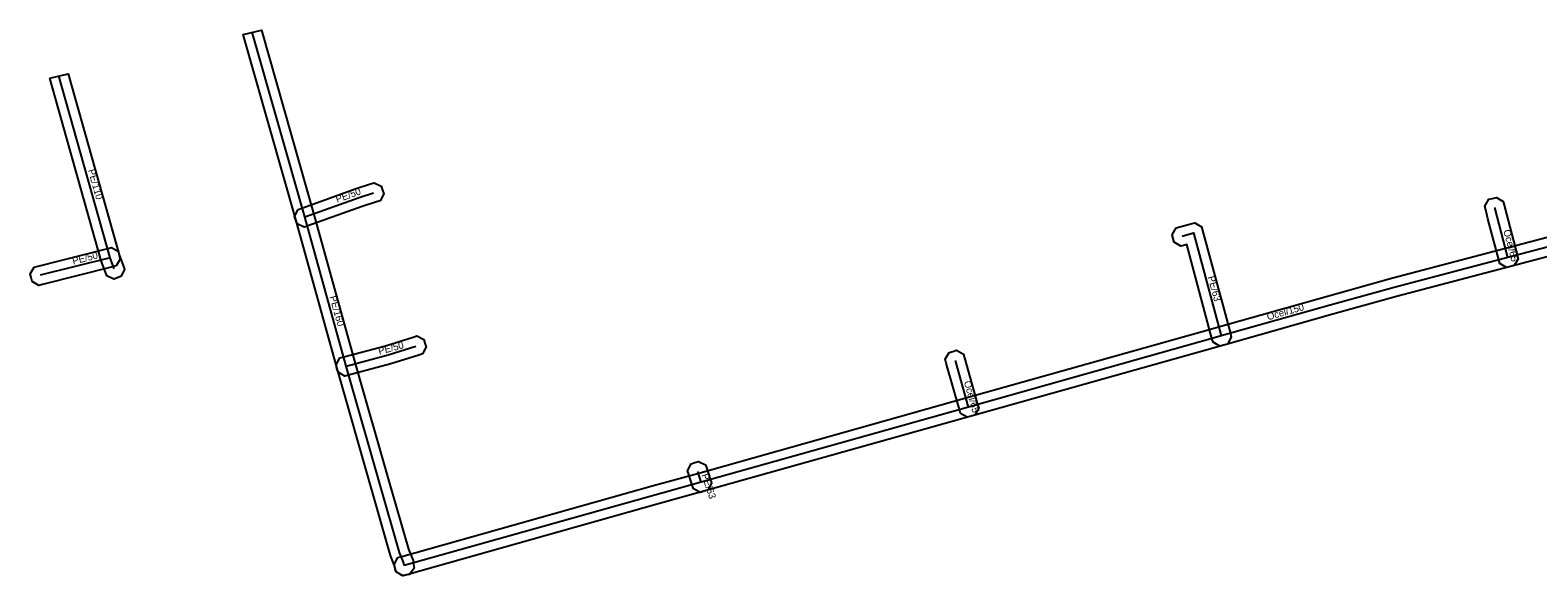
# Model space of a CAD drawing. Extents: x -599265 to -598944, y -1158962 to -1158820.
# Drawn here: x -599265.1 to -599106.1, y -1158937 to -1158879.4 of the extents above; entities that cross this region are included whole.
import ezdxf

# ---------------------------------------------------------------- set-up
doc = ezdxf.new("R2010")
doc.units = 0
for name, color, linetype in [('1', 7, 'Continuous'), ('14', 7, 'Continuous'), ('20', 7, 'Continuous')]:
    doc.layers.add(name, color=color, linetype=linetype)

msp = doc.modelspace()

# ---------------------------------------------------------------- linework, layer by layer
at = {"layer": '1'}
for points in [[(-599237.09, -1158899.41), (-599242.65, -1158879.89), (-599240.7, -1158879.45), (-599235.17, -1158898.87), (-599230.81, -1158914.59), (-599227.26, -1158927), (-599225.2, -1158934.18), (-599224.72, -1158935.37), (-599224.66, -1158935.75), (-599224.6, -1158936.16), (-599225.09, -1158936.82), (-599225.5, -1158936.89), (-599225.91, -1158936.95), (-599226.58, -1158936.46), (-599226.64, -1158936.05), (-599226.66, -1158935.91), (-599227.1, -1158934.84), (-599229.18, -1158927.54), (-599232.73, -1158915.13)], [(-599263.03, -1158884.5), (-599261.07, -1158884.05), (-599255.71, -1158903.13), (-599255.28, -1158904.26), (-599255.14, -1158904.65), (-599255.48, -1158905.4), (-599255.87, -1158905.55), (-599256.26, -1158905.69), (-599257.01, -1158905.35), (-599257.16, -1158904.96), (-599257.61, -1158903.75)], [(-599236.85, -1158898.34), (-599236.46, -1158898.2), (-599230.72, -1158896.15), (-599229.2, -1158895.66), (-599228.81, -1158895.53), (-599228.07, -1158895.91), (-599227.94, -1158896.3), (-599227.81, -1158896.7), (-599228.19, -1158897.43), (-599228.58, -1158897.56), (-599230.08, -1158898.05), (-599235.8, -1158900.08), (-599236.19, -1158900.22), (-599236.93, -1158899.86), (-599237.07, -1158899.48), (-599237.21, -1158899.08)], [(-599110.14, -1158904.06), (-599110.25, -1158903.66), (-599111.39, -1158899.35), (-599111.63, -1158898.4), (-599111.73, -1158897.99), (-599111.31, -1158897.28), (-599110.91, -1158897.18), (-599110.5, -1158897.08), (-599109.79, -1158897.5), (-599109.69, -1158897.91), (-599109.45, -1158898.85), (-599108.31, -1158903.14), (-599108.21, -1158903.54), (-599108.62, -1158904.26), (-599109.02, -1158904.37), (-599109.42, -1158904.47)], [(-599144.28, -1158900.3), (-599143.88, -1158900.19), (-599142.7, -1158899.87), (-599142.3, -1158899.76), (-599141.95, -1158899.97), (-599141.58, -1158900.18), (-599141.48, -1158900.57), (-599138.55, -1158911.43), (-599138.45, -1158911.83), (-599138.86, -1158912.54), (-599139.26, -1158912.65), (-599139.66, -1158912.76), (-599140.38, -1158912.35), (-599140.49, -1158911.95), (-599143.15, -1158902.06), (-599143.36, -1158902.12), (-599143.76, -1158902.23), (-599144.47, -1158901.81), (-599144.58, -1158901.41), (-599144.69, -1158901.01)], [(-599256.01, -1158904.31), (-599256.42, -1158904.41), (-599263.78, -1158906.26), (-599264.18, -1158906.36), (-599264.89, -1158905.94), (-599264.99, -1158905.53), (-599265.09, -1158905.13), (-599264.67, -1158904.42), (-599264.26, -1158904.32), (-599256.9, -1158902.47), (-599256.5, -1158902.37), (-599255.79, -1158902.79), (-599255.69, -1158903.2), (-599255.59, -1158903.6)], [(-599232.43, -1158914), (-599232.03, -1158913.89), (-599227.61, -1158912.71), (-599224.72, -1158911.8), (-599224.33, -1158911.67), (-599223.59, -1158912.05), (-599223.47, -1158912.45), (-599223.34, -1158912.84), (-599223.72, -1158913.58), (-599224.12, -1158913.7), (-599227.05, -1158914.63), (-599231.51, -1158915.83), (-599231.91, -1158915.93), (-599232.63, -1158915.52), (-599232.74, -1158915.12), (-599232.84, -1158914.72)], [(-599167.01, -1158919.85), (-599167.12, -1158919.45), (-599168.5, -1158914.54), (-599168.61, -1158914.14), (-599168.21, -1158913.42), (-599167.81, -1158913.31), (-599167.41, -1158913.2), (-599166.69, -1158913.6), (-599166.58, -1158914), (-599165.2, -1158918.91), (-599165.08, -1158919.31), (-599165.49, -1158920.03), (-599165.89, -1158920.14), (-599166.29, -1158920.26)], [(-599195.15, -1158927.81), (-599195.28, -1158927.42), (-599195.65, -1158926.3), (-599195.78, -1158925.91), (-599195.41, -1158925.17), (-599195.02, -1158925.03), (-599194.62, -1158924.91), (-599193.88, -1158925.28), (-599193.75, -1158925.67), (-599193.38, -1158926.78), (-599193.25, -1158927.18), (-599193.62, -1158927.92), (-599194.02, -1158928.05), (-599194.41, -1158928.18)]]:
    msp.add_lwpolyline(points, close=True, dxfattribs=at)
msp.add_lwpolyline([(-599102.75, -1158902.72), (-599109.03, -1158904.37), (-599121.03, -1158907.53), (-599127.76, -1158909.4), (-599139.25, -1158912.65), (-599140.11, -1158912.89), (-599165.89, -1158920.14), (-599194.06, -1158928.06), (-599198.97, -1158929.42), (-599225.38, -1158936.86), (-599225.78, -1158936.98), (-599226.5, -1158936.57), (-599226.61, -1158936.17), (-599226.72, -1158935.77), (-599226.32, -1158935.05), (-599225.92, -1158934.94), (-599199.51, -1158927.5), (-599194.6, -1158926.14), (-599166.43, -1158918.22), (-599140.65, -1158910.97), (-599139.79, -1158910.73), (-599128.3, -1158907.48), (-599121.55, -1158905.6), (-599109.54, -1158902.43), (-599103.27, -1158900.78)], dxfattribs=at)
at = {"layer": '14'}
for points in [[(-599225.65, -1158935.9), (-599225.69, -1158935.64), (-599226.15, -1158934.51), (-599228.22, -1158927.27), (-599231.77, -1158914.86), (-599236.13, -1158899.14), (-599241.67, -1158879.67)], [(-599256.22, -1158904.61), (-599256.66, -1158903.44), (-599262.05, -1158884.28)], [(-599042.76, -1158885.49), (-599068.42, -1158892.17), (-599094.54, -1158899.36), (-599103.01, -1158901.75), (-599109.28, -1158903.4), (-599121.29, -1158906.57), (-599128.03, -1158908.44), (-599139.52, -1158911.69), (-599140.38, -1158911.93), (-599166.16, -1158919.18), (-599194.33, -1158927.1), (-599199.24, -1158928.46), (-599225.65, -1158935.9)], [(-599236.13, -1158899.14), (-599230.4, -1158897.1), (-599228.89, -1158896.61)], [(-599109.28, -1158903.4), (-599110.42, -1158899.1), (-599110.66, -1158898.15)], [(-599143.62, -1158901.15), (-599142.44, -1158900.83), (-599139.52, -1158911.69)], [(-599256.66, -1158903.44), (-599264.02, -1158905.29)], [(-599231.77, -1158914.86), (-599227.33, -1158913.67), (-599224.42, -1158912.75)], [(-599166.16, -1158919.18), (-599167.54, -1158914.27)], [(-599194.33, -1158927.1), (-599194.7, -1158925.98)]]:
    msp.add_lwpolyline(points, dxfattribs=at)

# ---------------------------------------------------------------- texts
at = {"layer": '20'}
for s, rotation, p in [('PE/110', 285.7071, (-599259, -1158894.21)), ('PE/50', 19.5968, (-599232.72, -1158897.65)), ('Ocel/65', 284.8485, (-599109.78, -1158900.58)), ('PE/50', 14.1095, (-599260.54, -1158904.17)), ('PE/63', 285.0749, (-599140.94, -1158905.47)), ('PE/160', 285.5016, (-599233.54, -1158907.56)), ('Ocel/150', 15.78, (-599134.58, -1158910.04)), ('PE/50', 15.0037, (-599228.28, -1158913.67)), ('Ocel/65', 285.6985, (-599166.65, -1158916.53)), ('PE/63', 288.3887, (-599194.32, -1158926.34))]:
    msp.add_text(s, height=0.75, rotation=rotation, dxfattribs=at).set_placement(p)

doc.saveas('drawing.dxf')
